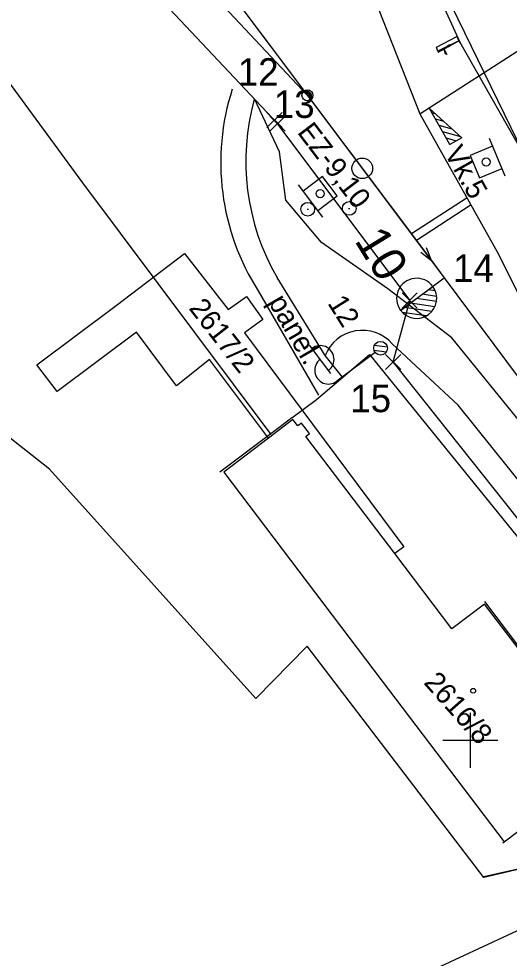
# Model space of a CAD drawing. Extents: x -804166 to -803706, y -1151030 to -1150147.
# Drawn here: x -803932.9 to -803897.2, y -1150515.9 to -1150447.5 of the extents above; entities that cross this region are included whole.
import ezdxf

# ---------------------------------------------------------------- set-up
doc = ezdxf.new("R2010")
doc.units = 0
for name, color, linetype in [('0381KM032-037P - Vrstva 1', 7, 'Continuous'), ('0381KM032-037P - Vrstva 17', 7, 'Continuous'), ('0381KM032-037P - Vrstva 19', 7, 'Continuous'), ('0381KM032-037P - Vrstva 2', 7, 'Continuous'), ('0381KM032-037P - Vrstva 23', 7, 'Continuous'), ('0381KM032-037P - Vrstva 25', 7, 'Continuous'), ('0381KM032-037P - Vrstva 27', 7, 'Continuous'), ('0381KM032-037P - Vrstva 3', 7, 'Continuous'), ('0381KM032-037P - Vrstva 4', 7, 'Continuous'), ('0381KM032-037P - Vrstva 49', 7, 'Continuous'), ('0381KM032-037P - Vrstva 51', 7, 'Continuous'), ('0381KM032-037P - Vrstva 55', 7, 'Continuous'), ('0381KM032-037P - Vrstva 57', 7, 'Continuous'), ('0381KM032-037P - Vrstva 59', 7, 'Continuous'), ('0381KM032-037P - Vrstva 7', 7, 'Continuous'), ('Default', 7, 'Continuous'), ('hran DP - hran DP', 7, 'Continuous'), ('krizky_1000 - Vrstva 1', 7, 'Continuous'), ('PSR_C2_2_Lomove_body_Vimperk - Vrstva 60', 7, 'Continuous'), ('PSR_C2_2_trasa_Vimperk - Kabelová trasa', 7, 'Continuous')]:
    doc.layers.add(name, color=color, linetype=linetype)

msp = doc.modelspace()

# ---------------------------------------------------------------- linework, layer by layer
at = {"layer": '0381KM032-037P - Vrstva 1'}
msp.add_line((-803901.897, -1150466.329), (-803893.522, -1150477.59), dxfattribs=at)
for points in [[(-804011.14, -1150262.39), (-804005.45, -1150273.41), (-803998.73, -1150284.85), (-803991.51, -1150295.63), (-803978.8, -1150312.77), (-803963.69, -1150332.99), (-803952.21, -1150348.36), (-803946.3, -1150356.39), (-803941.6, -1150363.14), (-803936.71, -1150370.83), (-803932.05, -1150378.84), (-803927.78, -1150386.91), (-803924.06, -1150395.18), (-803920.62, -1150403.65), (-803918.06, -1150410.86), (-803915.07, -1150420.32), (-803912.96, -1150427.25), (-803910.49, -1150435.34), (-803907.334, -1150445.05), (-803903.668, -1150454.381), (-803897.938, -1150464.596), (-803891.973, -1150476.598)], [(-803975.617, -1150392.296), (-803939.473, -1150444.116), (-803928.265, -1150459.416), (-803914.534, -1150477.731)], [(-803921.855, -1150439.729), (-803911.864, -1150453.035), (-803902.83, -1150465.067), (-803901.897, -1150466.329)], [(-803923.249, -1150440.918), (-803911.864, -1150453.035), (-803902.83, -1150465.067), (-803901.897, -1150466.329)]]:
    msp.add_lwpolyline(points, dxfattribs=at)
at = {"layer": '0381KM032-037P - Vrstva 17'}
msp.add_line((-803911.209, -1150475.173), (-803907.336, -1150471.899), dxfattribs=at)
for points in [[(-803907.336, -1150471.899), (-803888.961, -1150494.568)], [(-803912.992, -1150476.532), (-803911.209, -1150475.173)], [(-803888.027, -1150495.776), (-803886.131, -1150498.244), (-803887.49, -1150506.275), (-803890.053, -1150507.927), (-803899.02, -1150509.954)]]:
    msp.add_lwpolyline(points, dxfattribs=at)
at = {"layer": '0381KM032-037P - Vrstva 19'}
for p, q in [((-803902.473, -1150449.514), (-803900.978, -1150448.743)), ((-803900.978, -1150448.743), (-803900.834, -1150449.068)), ((-803902.371, -1150449.816), (-803902.473, -1150449.514)), ((-803900.834, -1150449.068), (-803902.371, -1150449.816)), ((-803902.35, -1150449.879), (-803900.834, -1150449.068)), ((-803902.371, -1150449.816), (-803902.35, -1150449.879)), ((-803901.816, -1150449.998), (-803901.912, -1150449.697))]:
    msp.add_line(p, q, dxfattribs=at)
for points in [[(-803900.834, -1150449.068), (-803900.834, -1150449.068), (-803900.774, -1150449.197)], [(-803901.912, -1150449.697), (-803901.906, -1150449.663), (-803901.715, -1150450.066), (-803901.816, -1150449.998)]]:
    msp.add_lwpolyline(points, dxfattribs=at)
msp.add_ellipse((-803901.564, -1150449.426), major_axis=(0.129, 0.077), ratio=0.428282, dxfattribs=at)
at = {"layer": '0381KM032-037P - Vrstva 2'}
for p, q in [((-803921.855, -1150439.729), (-803911.864, -1150453.035)), ((-803905.077, -1150468.694), (-803901.897, -1150466.329)), ((-803905.085, -1150468.688), (-803902.731, -1150466.949)), ((-803902.551, -1150467.276), (-803903.068, -1150467.199)), ((-803902.467, -1150468.058), (-803903.933, -1150467.837)), ((-803902.453, -1150467.676), (-803903.501, -1150467.519)), ((-803905.084, -1150468.689), (-803905.085, -1150468.688)), ((-803902.804, -1150468.776), (-803904.798, -1150468.476)), ((-803902.579, -1150468.425), (-803904.366, -1150468.157)), ((-803903.204, -1150469.1), (-803904.955, -1150468.837))]:
    msp.add_line(p, q, dxfattribs=at)
for points in [[(-803923.249, -1150440.918), (-803911.864, -1150453.035), (-803901.897, -1150466.329)], [(-803903.617, -1150464.45), (-803902.83, -1150465.067), (-803903.203, -1150464.139)]]:
    msp.add_lwpolyline(points, dxfattribs=at)
msp.add_circle((-803911.864, -1150453.035), 0.4, dxfattribs=at)
for centre, radius, start, end in [((-803903.907, -1150467.817), 1.462, 36.40566, 216.87518), ((-803903.907, -1150467.818), 1.464, 216.49519, 36.45604)]:
    msp.add_arc(centre, radius, start, end, dxfattribs=at)
at = {"layer": '0381KM032-037P - Vrstva 23'}
for points in [[(-803912.992, -1150476.532), (-803913.943, -1150477.255), (-803918.261, -1150480.471)], [(-803897.633, -1150507.469), (-803890, -1150501.72), (-803898.947, -1150489.885)]]:
    msp.add_lwpolyline(points, dxfattribs=at)
at = {"layer": '0381KM032-037P - Vrstva 25'}
for p, q in [((-803910.152, -1150473.302), (-803911.72, -1150471.228)), ((-803906.046, -1150471.376), (-803906.995, -1150471.244)), ((-803906.938, -1150471.75), (-803909.73, -1150473.861)), ((-803906.134, -1150471.742), (-803907.006, -1150471.621))]:
    msp.add_line(p, q, dxfattribs=at)
msp.add_circle((-803906.539, -1150471.449), 0.5, dxfattribs=at)
msp.add_circle((-803906.539, -1150471.449), 0.5, dxfattribs=at)
for centre, start, end in [((-803910.926, -1150472.258), 306.37771, 127.78285), ((-803910.333, -1150473.063), 127.08028, 307.08028)]:
    msp.add_arc(centre, 1, start, end, dxfattribs=at)
at = {"layer": '0381KM032-037P - Vrstva 27'}
msp.add_line((-803908.868, -1150461.265), (-803908.768, -1150461.265), dxfattribs=at)
msp.add_circle((-803908.818, -1150461.265), 0.5, dxfattribs=at)
at = {"layer": '0381KM032-037P - Vrstva 3'}
for p, q in [((-803903.668, -1150454.381), (-803871.126, -1150433.376)), ((-803902.805, -1150454.284), (-803902.575, -1150454.349)), ((-803902.546, -1150454.747), (-803901.955, -1150454.913)), ((-803902.286, -1150455.209), (-803901.335, -1150455.477)), ((-803902.027, -1150455.672), (-803900.714, -1150456.041)), ((-803901.767, -1150456.134), (-803901.031, -1150456.341)), ((-803897.459, -1150458.912), (-803898.603, -1150456.186)), ((-803901.508, -1150456.596), (-803901.493, -1150456.601)), ((-803898.374, -1150456.731), (-803900.01, -1150457.418)), ((-803900.01, -1150457.418), (-803899.323, -1150459.053)), ((-803899.323, -1150459.053), (-803897.688, -1150458.367)), ((-803910.778, -1150458.946), (-803912.19, -1150460.02)), ((-803909.704, -1150460.358), (-803910.778, -1150458.946)), ((-803912.548, -1150459.549), (-803910.758, -1150461.903)), ((-803911.116, -1150461.432), (-803909.704, -1150460.358))]:
    msp.add_line(p, q, dxfattribs=at)
msp.add_lwpolyline([(-803902.97, -1150453.99), (-803900.63, -1150456.117), (-803901.503, -1150456.606), (-803902.97, -1150453.99)], dxfattribs=at)
for centre in [(-803898.85, -1150457.89), (-803910.945, -1150460.191)]:
    msp.add_circle(centre, 0.296, dxfattribs=at)
at = {"layer": '0381KM032-037P - Vrstva 4'}
msp.add_line((-803875.88, -1150504.253), (-803939.777, -1150533.943), dxfattribs=at)
at = {"layer": '0381KM032-037P - Vrstva 49'}
msp.add_lwpolyline([(-803877.416, -1150484.532), (-803894.615, -1150460.334), (-803907.648, -1150433.624), (-803908.812, -1150430.908)], dxfattribs=at)
at = {"layer": '0381KM032-037P - Vrstva 51'}
for p, q in [((-803915.743, -1150453.306), (-803915.72, -1150453.288)), ((-803915.449, -1150467.279), (-803911.051, -1150474.867)), ((-803900.893, -1150475.608), (-803905.683, -1150471.142))]:
    msp.add_line(p, q, dxfattribs=at)
for points in [[(-803881.519, -1150497.913), (-803892.597, -1150481.46), (-803901.351, -1150470.694), (-803906.021, -1150467.127), (-803910.842, -1150463.746), (-803913.43, -1150460.674), (-803913.908, -1150457.138), (-803915.72, -1150453.288)], [(-803909.318, -1150473.555), (-803910.58, -1150471.975), (-803914.083, -1150466.31)], [(-803884.008, -1150499.305), (-803894.736, -1150483.244), (-803900.893, -1150475.608)]]:
    msp.add_lwpolyline(points, dxfattribs=at)
for centre, major_axis, ratio, start_param, end_param in [((-803900.854, -1150457.933), (3.992, -16.878), 0.999168, 4.166515, 5.049488), ((-803899.462, -1150457.838), (3.305, -16.585), 0.999136, 4.244568, 5.04061), ((-803907.875, -1150473.065), (-1.906, 2.208), 0.999734, 4.72036, 6.75861)]:
    msp.add_ellipse(centre, major_axis=major_axis, ratio=ratio, start_param=start_param, end_param=end_param, dxfattribs=at)
at = {"layer": '0381KM032-037P - Vrstva 55'}
for points in [[(-803914.71, -1150478.01), (-803919.01, -1150472.26), (-803921.41, -1150474.2), (-803924.33, -1150470.27), (-803930.11, -1150474.6), (-803931.57, -1150472.66), (-803925.79, -1150468.33), (-803920.83, -1150464.56), (-803917.63, -1150468.64), (-803916.3, -1150467.69), (-803915.12, -1150469.35), (-803916.46, -1150470.34), (-803904.84, -1150485.91), (-803905.5, -1150486.41)], [(-803901.34, -1150491.89), (-803905.5, -1150486.41), (-803911.98, -1150477.87), (-803911.71, -1150477.67), (-803912.3, -1150476.91), (-803912.56, -1150477.11), (-803912.92, -1150476.64), (-803914.71, -1150478.01), (-803917.95, -1150480.48), (-803906.42, -1150495.69), (-803897.53, -1150507.41), (-803890.06, -1150501.75), (-803898.96, -1150490.08), (-803901.34, -1150491.89)]]:
    msp.add_lwpolyline(points, dxfattribs=at)
at = {"layer": '0381KM032-037P - Vrstva 59'}
msp.add_circle((-803899.791, -1150496.398), 0.175, dxfattribs=at)
at = {"layer": '0381KM032-037P - Vrstva 7'}
for p, q in [((-803900.24, -1150460.491), (-803904.286, -1150463.128)), ((-803899.946, -1150461.016), (-803903.925, -1150463.609)), ((-803911.896, -1150461.333), (-803911.796, -1150461.333))]:
    msp.add_line(p, q, dxfattribs=at)
for centre, radius in [((-803907.873, -1150458.35), 0.75), ((-803911.846, -1150461.333), 0.5)]:
    msp.add_circle(centre, radius, dxfattribs=at)
at = {"layer": 'hran DP - hran DP'}
for p, q in [((-803907.15, -1150435.03), (-803900.76, -1150449.16)), ((-803900.76, -1150449.16), (-803893.94, -1150461.19)), ((-803930.65, -1150480.27), (-803944.36, -1150469.51)), ((-803915.62, -1150496.95), (-803930.65, -1150480.27)), ((-803911.88, -1150493.16), (-803915.62, -1150496.95)), ((-803899.02, -1150510.01), (-803911.88, -1150493.16)), ((-803890.08, -1150507.89), (-803899.02, -1150510.01))]:
    msp.add_line(p, q, dxfattribs=at)
at = {"layer": 'krizky_1000 - Vrstva 1'}
for points in [[(-803900, -1150498), (-803900, -1150502)], [(-803902, -1150500), (-803898, -1150500)]]:
    msp.add_lwpolyline(points, dxfattribs=at)
at = {"layer": 'PSR_C2_2_Lomove_body_Vimperk - Vrstva 60'}
for p, q in [((-803914.814, -1150455.385), (-803913.714, -1150454.285)), ((-803913.714, -1150455.385), (-803914.814, -1150454.285)), ((-803914.6, -1150455.639), (-803913.5, -1150454.539)), ((-803913.5, -1150455.639), (-803914.6, -1150454.539)), ((-803904.964, -1150468.523), (-803903.864, -1150467.423)), ((-803903.864, -1150468.523), (-803904.964, -1150467.423)), ((-803906.173, -1150473.002), (-803905.073, -1150471.902)), ((-803905.073, -1150473.002), (-803906.173, -1150471.902))]:
    msp.add_line(p, q, dxfattribs=at)
at = {"layer": 'PSR_C2_2_trasa_Vimperk - Kabelová trasa'}
for p, q in [((-803926.955, -1150441.355), (-803914.05, -1150455.089)), ((-803914.264, -1150454.835), (-803904.414, -1150467.973))]:
    msp.add_line(p, q, dxfattribs=at)
msp.add_lwpolyline([(-803884.501, -1150499.004), (-803905.623, -1150472.452), (-803904.414, -1150467.973)], dxfattribs=at)

# ---------------------------------------------------------------- texts
at = {"layer": '0381KM032-037P - Vrstva 2'}
msp.add_text('10', height=2.5, rotation=301.47562, dxfattribs=at).set_placement((-803908.478, -1150463.606))
at = {"layer": '0381KM032-037P - Vrstva 25'}
msp.add_text('12', height=1.5, rotation=302.08028, dxfattribs=at).set_placement((-803910.438, -1150468.167))
at = {"layer": '0381KM032-037P - Vrstva 3'}
for s, rotation, p in [('EZ-9,10', 307.24913, (-803912.657, -1150455.735)), ('Vk.5', 299.2898, (-803901.935, -1150457.221))]:
    msp.add_text(s, height=1.5, rotation=rotation, dxfattribs=at).set_placement(p)
at = {"layer": '0381KM032-037P - Vrstva 51'}
msp.add_text('panel.', height=1.5, rotation=300.09655, dxfattribs=at).set_placement((-803914.767, -1150468.073))
at = {"layer": '0381KM032-037P - Vrstva 57'}
for s, rotation, p in [('2617/2', 308.0366, (-803920.561, -1150468.55)), ('2616/8', 311.46226, (-803903.451, -1150495.836))]:
    msp.add_text(s, height=1.5, rotation=rotation, dxfattribs=at).set_placement(p)
at = {"layer": 'Default'}
for s, p in [('12', (-803916.945, -1150452.329)), ('13', (-803914.316, -1150454.677)), ('14', (-803901.262, -1150466.617)), ('15', (-803908.746, -1150476.108))]:
    msp.add_text(s, height=2, dxfattribs=at).set_placement(p)

doc.saveas('drawing.dxf')
